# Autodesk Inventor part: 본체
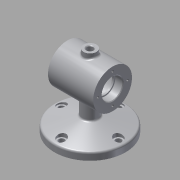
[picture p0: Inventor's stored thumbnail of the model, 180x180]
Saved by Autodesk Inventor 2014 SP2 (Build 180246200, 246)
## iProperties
Created: 2018-12
Part Number: 본체
Material: 알루미늄 6061
Document SubType Name: Modeling
Designer: 거성
Density: 2.71 g/cm^3
Appearance: 알루미늄 - 평지
Mass: 687.638 g
Surface Area: 555.676 cm^2
Volume: 253.741 cm^3
Author: 거성
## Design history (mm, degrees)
sketch "스케치1"
  geometry: L1 (-35, 30)-(35, 30); L2 (35, 30)-(35, 0); L3 (35, 0)-(-35, 0); L4 (-35, 0)-(-35, 30); 2 further points
  constraints: 8 end point, 2 parallel, 1 coincident, 1 horizontal, 1 midpoint, 1 perpendicular
  dimensions: "d0" = 70 distance of L2.end L3.end; "d1" = 30 distance of L3.end L1.start
revolve "회전1" sketch "스케치1" stored, may be unused: angle "d2" = 90 deg
sketch "스케치2"
  geometry: L1 (-35, 30)-(-35, -30) reference; L2 (35, 30)-(35, -30) reference; L3 (-35, 0)-(35, 0); L4 (0, 0)-(0, 26.689); L5 (-35, 0)-(-35, 16); L6 (-35, 30)-(-35, -30) reference; L7 (-23, 15.7)-(-23, 14); L8 (-35, 16)-(-23.3, 16); L9 (-23, 14)-(-20, 14); L10 (-20, 14)-(-20, 22); L11 (-17, 25)-(0, 25); L12 (23, 15.7)-(23, 14); L13 (35, 16)-(23.3, 16); L14 (23, 14)-(20, 14); L15 (20, 14)-(20, 22); L16 (35, 30)-(35, -30); L17 (17, 25)-(0, 25); L18 (35, 16)-(35, 0); A1 r 3 centre (-17, 22) between (-17, 25) and (-20, 22); A2 r 3 centre (17, 22) between (20, 22) and (17, 25); A3 r 0.3 centre (-23.3, 15.7) between (-23, 15.7) and (-23.3, 16); A4 r 0.3 centre (23.3, 15.7) between (23.3, 16) and (23, 15.7); 4 further points
  constraints: 30 end point, 10 point on line, 8 point on circle, 8 tangent, 5 symmetric about line, 4 centre point, 3 parallel, 3 perpendicular, 2 midpoint, 1 collinear, 1 equal radius
  dimensions: "d3" = 32 diameter of L8 L3; "d4" = 28 diameter of L9 L3; "d5" = 50 diameter of L11 L3; "d6" = 12 distance of L5.end point (-23, 16); "d7" = 20 distance of point (-20, 25) L11.end; "d54" = 3 radius of A1; "d55" = 0.3 radius of A3; "d56" = 0.3 radius of A4
revolve "회전2" sketch "스케치2" stored, may be unused: angle "d8" = 90 deg
node "작업 평면2"
sketch "스케치3"
  geometry: C1 r 55 at (0, 0); 1 further point
  constraints: 1 centre point, 1 coincident
  dimensions: "d11" = 110 diameter of C1
extrude "돌출1" join sketch "스케치3" distance "d12" = 11; taper "d13" = 0 deg
sketch "스케치4"
  geometry: L1 (55, -64)-(-55, -64) reference; L2 (0, -64)-(0, -49.263); L3 (-55, -64)-(0, -49.263); 1 further point
  constraints: 4 end point, 1 midpoint, 1 perpendicular
  dimensions: "d14" = 15 deg angle of L1 L3
revolve "회전3" sketch "스케치4" stored, may be unused: angle "d15" = 90 deg
node "작업 평면3"
sketch "스케치5"
  geometry: C1 r 12 at (0, 0); 1 further point
  constraints: 1 centre point, 1 coincident
  dimensions: "d17" = 24 diameter of C1
extrude "돌출2" join sketch "스케치5" stored distance "d18" = 10; taper "d19" = 0 deg
sketch "스케치6"
  geometry: A1 r 12 centre (0, 0) between (12, 0) and (-12, 0) reference; A2 r 12 centre (0, 0) between (-12, 0) and (12, 0) reference
extrude "돌출3" join sketch "스케치6" stored distance "d20" = 10; taper "d21" = 0 deg
node "작업 평면4"
sketch "스케치7"
  geometry: C1 r 10 at (0, 0); 1 further point
  constraints: 1 centre point, 1 coincident
  dimensions: "d23" = 20 diameter of C1
extrude "돌출4" join sketch "스케치7" stored distance "d24" = 10; taper "d25" = 0 deg
sketch "스케치8"
  geometry: C1 r 10 at (0, 0) reference; C2 r 5 at (0, 0)
  constraints: 1 centre point, 1 coincident
  dimensions: "d26" = 10 diameter of C2
extrude "돌출5" cut sketch "스케치8" stored distance "d27" = 10; taper "d28" = 0 deg
sketch "스케치9"
  geometry: C1 r 16 at (0, 0) reference; 1 further point
  constraints: 1 vertical alignment
  dimensions: "d29" = 23 distance of C1.centre point (0, 23)
hole "구멍1" sketch "스케치9" at (0, 23) diameter "d30" = 3.242; stored, may be unused: countersink angle "d34" = 90 deg, drill point angle "d36" = 118 deg; dims "d31" = 8, "d32" = 4, "d33" = 2, "d35" = 10
sketch "스케치10"
  geometry: C1 r 55 at (0, 0) reference; 1 further point
  constraints: 1 vertical alignment
  dimensions: "d40" = 44 distance of C1.centre point (0, 44)
hole "구멍2" sketch "스케치10" at (0, 44) diameter "d41" = 9; stored, may be unused: countersink angle "d45" = 90 deg, drill point angle "d47" = 0 deg; dims "d42" = 8, "d43" = 4, "d44" = 2, "d46" = 10
sketch "스케치11"
  geometry: C1 r 4.5 at (0, 0) reference; C2 r 7 at (0, 0); 1 further point
  constraints: 1 centre point, 1 coincident
  dimensions: "d48" = 14 diameter of C2
extrude "돌출6" cut sketch "스케치11" distance "d49" = 20; taper "d50" = 0 deg
fillet "모깎기1" dims "d57" = 3
chamfer "모따기1" distance "d58" = 1; stored, may be unused: second distance "d59" = 2, angle "d60" = 45 deg
node "작업 평면5"
sketch "스케치12"
  geometry: L1 (-24.778, 12.294)-(24.778, 12.294); L2 (24.778, 12.294)-(24.778, -12.294); L3 (24.778, -12.294)-(-24.778, -12.294); L4 (-24.778, -12.294)-(-24.778, 12.294); L5 (-24.778, 12.294)-(24.778, -12.294); L6 (35, 30)-(-35, 30) reference; L7 (-35, 30)-(-35, -30) reference; L8 (24.778, 12.294)-(-24.778, -12.294); 5 further points
  constraints: 4 end point, 4 midpoint, 1 horizontal alignment, 1 vertical alignment, 2 other
extrude "돌출7" join sketch "스케치12" stored distance "d62" = 0.5; taper "d63" = 0 deg
node "솔리드1"
pattern_circular "원형 패턴1" dims angle "d38" = 360 deg
mirror "대칭1"
pattern_circular "원형 패턴2" dims angle "d52" = 360 deg
node "투영된 루프1"
other parameters: "d10" = -75, "d22" = 37, "d61" = 30.5
